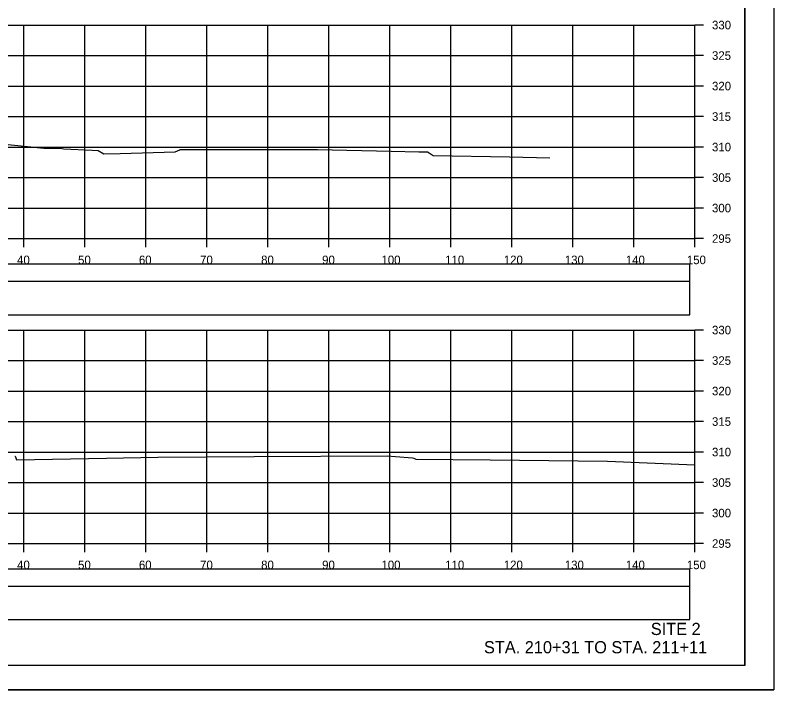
# Model space of a CAD drawing. Extents: x 1368122 to 1710785, y 373130 to 557566.
# Drawn here: x 1370060.8 to 1370185.2, y 375263.7 to 375374.3 of the extents above; entities that cross this region are included whole.
import ezdxf

# ---------------------------------------------------------------- set-up
doc = ezdxf.new("R2010")
doc.units = 0
for name, color, linetype in [('R_Axis', 7, 'Continuous'), ('R_Axis Annot', 7, 'Continuous'), ('R_Border', 7, 'Continuous'), ('R_Draft', 7, 'Continuous'), ('R_Exist Surface', 7, 'Continuous'), ('R_Grid', 7, 'Continuous'), ('R_No Plot', 7, 'Continuous')]:
    doc.layers.add(name, color=color, linetype=linetype)

msp = doc.modelspace()

# ---------------------------------------------------------------- linework, layer by layer
for points in [[(1369873.09, 375330.68), (1370171.39, 375330.68), (1370171.39, 375333.5), (1369873.09, 375333.5)], [(1369873.09, 375325.21), (1370171.39, 375325.21), (1370171.39, 375330.63), (1369873.09, 375330.63)], [(1369873.09, 375280.68), (1370171.39, 375280.68), (1370171.39, 375283.5), (1369873.09, 375283.5)], [(1369873.09, 375275.21), (1370171.39, 375275.21), (1370171.39, 375280.63), (1369873.09, 375280.63)]]:
    msp.add_lwpolyline(points, close=True)
at = {"layer": 'R_Axis'}
for p, q in [((1370172.24, 375337.69), (1370172.24, 375372.69)), ((1370173.64, 375372.69), (1370172.24, 375372.69)), ((1370173.64, 375367.69), (1370172.24, 375367.69)), ((1370173.64, 375362.69), (1370172.24, 375362.69)), ((1370173.64, 375357.69), (1370172.24, 375357.69)), ((1370173.64, 375352.69), (1370172.24, 375352.69)), ((1370173.64, 375347.69), (1370172.24, 375347.69)), ((1370173.64, 375342.69), (1370172.24, 375342.69)), ((1369872.24, 375337.69), (1370172.24, 375337.69)), ((1370062.24, 375336.29), (1370062.24, 375337.69)), ((1370072.24, 375336.29), (1370072.24, 375337.69)), ((1370082.24, 375336.29), (1370082.24, 375337.69)), ((1370092.24, 375336.29), (1370092.24, 375337.69)), ((1370102.24, 375336.29), (1370102.24, 375337.69)), ((1370112.24, 375336.29), (1370112.24, 375337.69)), ((1370122.24, 375336.29), (1370122.24, 375337.69)), ((1370132.24, 375336.29), (1370132.24, 375337.69)), ((1370142.24, 375336.29), (1370142.24, 375337.69)), ((1370152.24, 375336.29), (1370152.24, 375337.69)), ((1370162.24, 375336.29), (1370162.24, 375337.69)), ((1370172.24, 375336.29), (1370172.24, 375337.69)), ((1370173.64, 375337.69), (1370172.24, 375337.69)), ((1370172.24, 375287.69), (1370172.24, 375322.69)), ((1370173.64, 375322.69), (1370172.24, 375322.69)), ((1370173.64, 375317.69), (1370172.24, 375317.69)), ((1370173.64, 375312.69), (1370172.24, 375312.69)), ((1370173.64, 375307.69), (1370172.24, 375307.69)), ((1370173.64, 375302.69), (1370172.24, 375302.69)), ((1370173.64, 375297.69), (1370172.24, 375297.69)), ((1370173.64, 375292.69), (1370172.24, 375292.69)), ((1369872.24, 375287.69), (1370172.24, 375287.69)), ((1370062.24, 375286.29), (1370062.24, 375287.69)), ((1370072.24, 375286.29), (1370072.24, 375287.69)), ((1370082.24, 375286.29), (1370082.24, 375287.69)), ((1370092.24, 375286.29), (1370092.24, 375287.69)), ((1370102.24, 375286.29), (1370102.24, 375287.69)), ((1370112.24, 375286.29), (1370112.24, 375287.69)), ((1370122.24, 375286.29), (1370122.24, 375287.69)), ((1370132.24, 375286.29), (1370132.24, 375287.69)), ((1370142.24, 375286.29), (1370142.24, 375287.69)), ((1370152.24, 375286.29), (1370152.24, 375287.69)), ((1370162.24, 375286.29), (1370162.24, 375287.69)), ((1370172.24, 375286.29), (1370172.24, 375287.69)), ((1370173.64, 375287.69), (1370172.24, 375287.69))]:
    msp.add_line(p, q, dxfattribs=at)
at = {"layer": 'R_Border'}
for q in [(1370180.42, 375473.15), (1369864.24, 375267.69)]:
    msp.add_line((1370180.42, 375267.69), q, dxfattribs=at)
at = {"layer": 'R_Exist Surface'}
for points in [[(1370056.42, 375353.43), (1370065.56, 375352.52), (1370068.48, 375352.43), (1370068.8, 375352.41), (1370073.47, 375352.19), (1370074.4, 375352.15), (1370074.43, 375352.12), (1370075.38, 375351.6), (1370078.04, 375351.66), (1370087.08, 375351.91), (1370087.85, 375352.25), (1370087.9, 375352.27), (1370099.36, 375352.28), (1370110.38, 375352.28), (1370122.45, 375352.03), (1370127, 375351.91), (1370128.42, 375351.91), (1370128.69, 375351.75), (1370129.37, 375351.32), (1370141.84, 375351.07), (1370148.45, 375350.91)], [(1370060.79, 375301.99), (1370060.85, 375301.99), (1370060.87, 375301.91), (1370061.05, 375301.39), (1370075.79, 375301.7), (1370084.21, 375301.87), (1370100.02, 375301.96), (1370121.81, 375302.08), (1370123.15, 375301.97), (1370125.95, 375301.74), (1370126.18, 375301.66), (1370126.53, 375301.52), (1370138.68, 375301.4), (1370157.91, 375301.19), (1370172.24, 375300.57)]]:
    msp.add_lwpolyline(points, dxfattribs=at)
at = {"layer": 'R_Grid'}
for p, q in [((1369872.24, 375372.69), (1370172.24, 375372.69)), ((1370062.24, 375337.69), (1370062.24, 375372.69)), ((1370072.24, 375337.69), (1370072.24, 375372.69)), ((1370082.24, 375337.69), (1370082.24, 375372.69)), ((1370092.24, 375337.69), (1370092.24, 375372.69)), ((1370102.24, 375337.69), (1370102.24, 375372.69)), ((1370112.24, 375337.69), (1370112.24, 375372.69)), ((1370122.24, 375337.69), (1370122.24, 375372.69)), ((1370132.24, 375337.69), (1370132.24, 375372.69)), ((1370142.24, 375337.69), (1370142.24, 375372.69)), ((1370152.24, 375337.69), (1370152.24, 375372.69)), ((1370162.24, 375337.69), (1370162.24, 375372.69)), ((1370172.24, 375337.69), (1370172.24, 375372.69)), ((1369872.24, 375367.69), (1370172.24, 375367.69)), ((1369872.24, 375362.69), (1370172.24, 375362.69)), ((1369872.24, 375357.69), (1370172.24, 375357.69)), ((1369872.24, 375352.69), (1370172.24, 375352.69)), ((1369872.24, 375347.69), (1370172.24, 375347.69)), ((1369872.24, 375342.69), (1370172.24, 375342.69)), ((1369872.24, 375337.69), (1370172.24, 375337.69)), ((1369872.24, 375322.69), (1370172.24, 375322.69)), ((1370062.24, 375287.69), (1370062.24, 375322.69)), ((1370072.24, 375287.69), (1370072.24, 375322.69)), ((1370082.24, 375287.69), (1370082.24, 375322.69)), ((1370092.24, 375287.69), (1370092.24, 375322.69)), ((1370102.24, 375287.69), (1370102.24, 375322.69)), ((1370112.24, 375287.69), (1370112.24, 375322.69)), ((1370122.24, 375287.69), (1370122.24, 375322.69)), ((1370132.24, 375287.69), (1370132.24, 375322.69)), ((1370142.24, 375287.69), (1370142.24, 375322.69)), ((1370152.24, 375287.69), (1370152.24, 375322.69)), ((1370162.24, 375287.69), (1370162.24, 375322.69)), ((1370172.24, 375287.69), (1370172.24, 375322.69)), ((1369872.24, 375317.69), (1370172.24, 375317.69)), ((1369872.24, 375312.69), (1370172.24, 375312.69)), ((1369872.24, 375307.69), (1370172.24, 375307.69)), ((1369872.24, 375302.69), (1370172.24, 375302.69)), ((1369872.24, 375297.69), (1370172.24, 375297.69)), ((1369872.24, 375292.69), (1370172.24, 375292.69)), ((1369872.24, 375287.69), (1370172.24, 375287.69))]:
    msp.add_line(p, q, dxfattribs=at)
at = {"layer": 'R_No Plot'}
msp.add_line((1369851.84, 375263.71), (1370185.17, 375263.71), dxfattribs=at)
for points in [[(1369851.83, 375477.04), (1370185.17, 375477.04), (1370185.17, 375263.71), (1369851.83, 375263.71)], [(1370098.16, 375473.15), (1370117.78, 375473.15), (1370117.78, 375463.27), (1370133.89, 375463.27), (1370157.09, 375463.27), (1370157.21, 375435.11), (1370180.42, 375435.11), (1370180.42, 375267.69), (1369864.24, 375267.69), (1369864.24, 375473.15)]]:
    msp.add_lwpolyline(points, close=True, dxfattribs=at)

# ---------------------------------------------------------------- texts
at = {"layer": 'R_Axis Annot'}
for s, p in [('330', (1370175.04, 375371.99)), ('325', (1370175.04, 375366.99)), ('320', (1370175.04, 375361.99)), ('315', (1370175.04, 375356.99)), ('310', (1370175.04, 375351.99)), ('305', (1370175.04, 375346.99)), ('300', (1370175.04, 375341.99)), ('295', (1370175.04, 375336.99)), ('40', (1370061.15, 375333.49)), ('50', (1370071.15, 375333.49)), ('60', (1370081.12, 375333.49)), ('70', (1370091.15, 375333.49)), ('80', (1370101.15, 375333.49)), ('90', (1370111.15, 375333.49)), ('100', (1370120.87, 375333.49)), ('110', (1370131.32, 375333.49)), ('120', (1370140.92, 375333.49)), ('130', (1370150.92, 375333.49)), ('140', (1370160.92, 375333.49)), ('150', (1370170.92, 375333.49)), ('330', (1370175.04, 375321.99)), ('325', (1370175.04, 375316.99)), ('320', (1370175.04, 375311.99)), ('315', (1370175.04, 375306.99)), ('310', (1370175.04, 375301.99)), ('305', (1370175.04, 375296.99)), ('300', (1370175.04, 375291.99)), ('295', (1370175.04, 375286.99)), ('40', (1370061.15, 375283.49)), ('50', (1370071.15, 375283.49)), ('60', (1370081.12, 375283.49)), ('70', (1370091.15, 375283.49)), ('80', (1370101.15, 375283.49)), ('90', (1370111.15, 375283.49)), ('100', (1370120.87, 375283.49)), ('110', (1370131.32, 375283.49)), ('120', (1370140.92, 375283.49)), ('130', (1370150.92, 375283.49)), ('140', (1370160.92, 375283.49)), ('150', (1370170.92, 375283.49))]:
    msp.add_text(s, height=1.4, dxfattribs=at).set_placement(p)
at = {"layer": 'R_Draft'}
for s, p in [('SITE 2', (1370165.01, 375272.69)), ('STA. 210+31 TO STA. 211+11', (1370137.67, 375269.69))]:
    msp.add_text(s, height=2, dxfattribs=at).set_placement(p)

doc.saveas('drawing.dxf')
